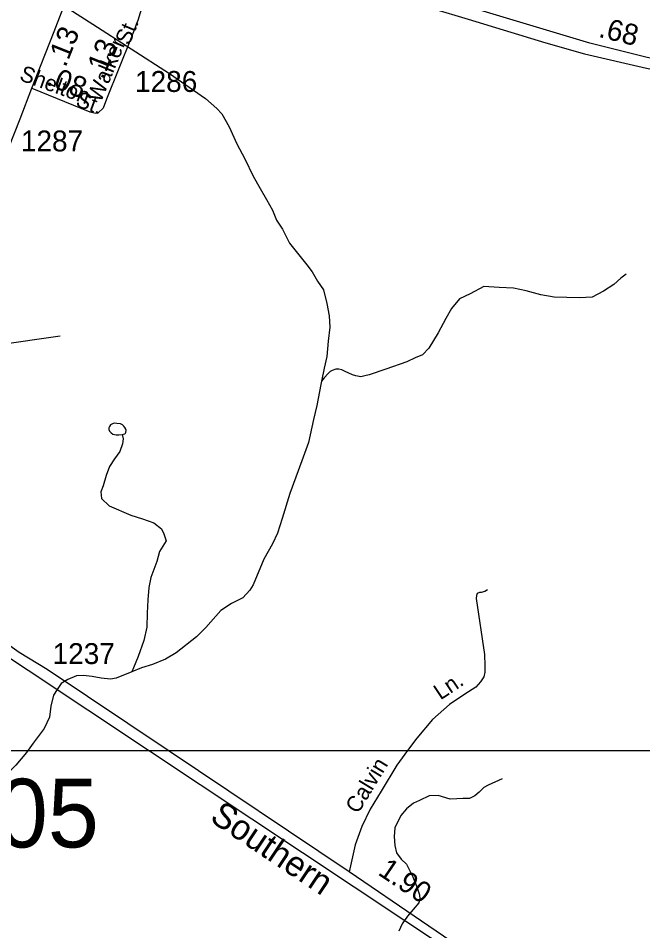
# Model space of a CAD drawing. Extents: x 2206922 to 2357709, y 510027 to 673830.
# Drawn here: x 2271615 to 2275344, y 609677 to 615129 of the extents above; entities that cross this region are included whole.
import ezdxf

# ---------------------------------------------------------------- set-up
doc = ezdxf.new("R2010")
doc.units = 0
for name, color, linetype in [('Exist Hydrographic Misc Water Feature', 7, 'Continuous'), ('Exist Railroad Mainline', 7, 'Continuous'), ('Exist Railroad Mainline Label', 7, 'Continuous'), ('Exist Road Non-System Type 51', 7, 'Continuous'), ('Exist Road Non-System Type 51 Label', 7, 'Continuous'), ('Exist Road Primary US Divided Attributed', 7, 'Continuous'), ('Exist Road Primary US Mileage Tenths English Label', 7, 'Continuous'), ('Exist Road Secondary Mileage Hundredths English Label', 7, 'Continuous'), ('Exist Road Secondary Structure Pipe Number Label', 7, 'Continuous'), ('Exist Road Secondary Type 51 Attributed', 7, 'Continuous'), ('Exist Road Secondary Type 51 Label', 7, 'Continuous'), ('Exist Road Secondary Type 51 Number Label', 7, 'Continuous'), ('Map Preparation Inset Cut Line', 7, 'Continuous')]:
    doc.layers.add(name, color=color, linetype=linetype)

msp = doc.modelspace()

# ---------------------------------------------------------------- linework, layer by layer
at = {"layer": 'Exist Hydrographic Misc Water Feature'}
for points in [[(2271915.8, 615185.7), (2272060.5, 615092.9), (2272517, 614799.5), (2272732.3, 614649.5), (2272800.6, 614590.5)], [(2272800.6, 614590.5), (2272831.1, 614556.7), (2272873.8, 614480.9), (2272920.7, 614377.7), (2272967.5, 614288), (2273016.5, 614184.4), (2273059.6, 614111), (2273097.5, 614045.3), (2273132.3, 613981.7), (2273157, 613922), (2273191.8, 613868.5), (2273234.3, 613784.6), (2273337.4, 613655.9), (2273370, 613614.1), (2273402.4, 613558.5), (2273436.6, 613506.7), (2273457.6, 613425.3), (2273471.9, 613351.3), (2273474.8, 613283.2), (2273465.4, 613199.4), (2273456.5, 613107.1), (2273441, 613037.2), (2273425.8, 612960.9)], [(2275244.8, 613599.6), (2275213.2, 613575.6), (2275171.6, 613537.3), (2275109.9, 613498.7), (2275042.2, 613461.9), (2274966.5, 613459.1), (2274890.3, 613460.4), (2274814.4, 613461.8), (2274736.1, 613477.2), (2274648.1, 613500.1), (2274572, 613515.7), (2274486.3, 613520.5), (2274394, 613525.9), (2274312.4, 613483), (2274248.9, 613452.5), (2274201.3, 613393.9), (2274167.7, 613335.7), (2274122.7, 613249.6), (2274065.7, 613156.8), (2274027.8, 613118.7), (2273984.3, 613100.1), (2273934.5, 613075.6), (2273809, 613032.5), (2273711, 612997.8), (2273683.3, 612991.4), (2273659.5, 612987.3), (2273631.2, 612993.2), (2273611.3, 612998.6), (2273567.5, 613018.2), (2273547, 613028.2), (2273528.9, 613032.1), (2273511.1, 613031.6), (2273489.3, 613023.5), (2273477.2, 613017.6), (2273465.6, 613005.6), (2273441.4, 612981.2), (2273425.8, 612960.9)], [(2273425.8, 612960.9), (2273424.1, 612951), (2273422.1, 612941.2), (2273397.1, 612814.7), (2273378, 612730.8), (2273347.2, 612594.3), (2273308.1, 612484.3), (2273236.1, 612289.5), (2273191.6, 612139.3), (2273162.3, 612052.8), (2273133, 611988.7), (2273081.9, 611896.2), (2273017.3, 611743.7), (2272998, 611711.8), (2272956.4, 611665.3), (2272888.3, 611632.6), (2272824.8, 611589.9), (2272735.8, 611489.3), (2272678.8, 611432.6), (2272557.6, 611337.7), (2272494.2, 611299), (2272416.3, 611268.6), (2272350.5, 611247.7), (2272292.9, 611223.1)], [(2272235.2, 612641.9), (2272251.2, 612646.4), (2272255.3, 612650.2), (2272257.4, 612654.4), (2272259.2, 612668.3), (2272256.8, 612674.3), (2272251.2, 612684.1), (2272244.9, 612691.9), (2272237.3, 612700), (2272224.8, 612705.9), (2272202.8, 612707.6), (2272190.7, 612709.4), (2272180.7, 612707.3), (2272172.9, 612703.2), (2272164.9, 612699.1), (2272159, 612689.5), (2272155.1, 612681.1), (2272155.3, 612671.4), (2272159, 612661.5), (2272169.2, 612651.4), (2272179.5, 612643.4), (2272199.6, 612639.5), (2272215.4, 612640), (2272235.2, 612641.9)], [(2272235.2, 612641.9), (2272241.6, 612616.2), (2272237.9, 612585.9), (2272220.5, 612539.9), (2272188.9, 612495.6), (2272159.4, 612451.4), (2272139.7, 612397.1), (2272122.7, 612335.2), (2272106.9, 612299.1), (2272110.8, 612259.1), (2272157.5, 612215.6), (2272286.1, 612160.5), (2272356.2, 612137.4), (2272424.1, 612114.2), (2272470.4, 612078.4), (2272485, 612048.6), (2272497.1, 612006.7), (2272457.9, 611942.4), (2272442.6, 611882.3), (2272405.6, 611788.1), (2272393.7, 611727.8), (2272388.8, 611654), (2272383.5, 611574), (2272382.3, 611489.9), (2272365, 611411.8), (2272330, 611315.7), (2272302.3, 611247.2), (2272292.9, 611223.1)], [(2272292.9, 611223.1), (2272199.6, 611186.5), (2272165.3, 611180.3), (2272109.3, 611185.5), (2272055.2, 611196.9), (2272002.9, 611202.7), (2271963.3, 611200.2), (2271911.7, 611177.6), (2271871.5, 611153.6), (2271847.9, 611119), (2271824.3, 611084.9), (2271809.1, 611018.7), (2271801.6, 610952.8), (2271768.5, 610884.5), (2271703.1, 610797.8), (2271664, 610741.6), (2271600, 610666.9), (2271542.8, 610606.6), (2271507.5, 610560.4), (2271475.7, 610501.9), (2271454.6, 610453.6), (2271430.4, 610234.3)], [(2274503.7, 610584.6), (2274420.3, 610547.7), (2274394, 610533.4), (2274366.4, 610505.1), (2274340.5, 610483), (2274308.5, 610466.8), (2274269, 610466.2), (2274234.5, 610464.1), (2274193.3, 610463.5), (2274123, 610485), (2274068.8, 610482.2), (2274011, 610455.6), (2273975.5, 610439.5), (2273933.7, 610405.2), (2273900.1, 610364.9), (2273862.7, 610292.7), (2273859.1, 610240.5), (2273863.8, 610186.7), (2273873.8, 610142.6), (2273900.7, 610104.8), (2273932.7, 610075.3), (2273971.2, 609999.8), (2273994, 609939.9), (2274010.2, 609892.1), (2274012.6, 609866.2), (2274006.9, 609844.3), (2273973.5, 609803.9), (2273939.4, 609763.6), (2273908.1, 609717.3), (2273886.5, 609675.1)]]:
    msp.add_lwpolyline(points, dxfattribs=at)
at = {"layer": 'Exist Railroad Mainline'}
msp.add_lwpolyline([(2277075.8, 607647), (2275362.6, 608781.5), (2275266.2, 608845.4), (2273928.2, 609731.4), (2272391.5, 610753.3), (2270229, 612191.5), (2265356.3, 615416.5), (2265047.6, 615620.9), (2265047, 615621.2)], dxfattribs=at)
at = {"layer": 'Exist Road Non-System Type 51'}
msp.add_line((2271864.9, 613228.8), (2271313.5, 613151.1), dxfattribs=at)
for points in [[(2274417.3, 611713), (2274401.3, 611702.9), (2274379.4, 611698.7), (2274369.4, 611698.5), (2274355.5, 611692.4), (2274351.7, 611680.3), (2274349.7, 611662.4), (2274398.9, 611327.1), (2274401.5, 611259), (2274399.9, 611221.1), (2274394.2, 611193), (2274374.4, 611164.8), (2274346.7, 611132.6), (2274281.3, 611089.9), (2274189.9, 611029.2), (2274088.7, 610938.3), (2273993.9, 610827.5), (2273939.3, 610753.3)], [(2273939.3, 610753.3), (2273875.5, 610666.5), (2273780.9, 610511.7), (2273716, 610403.1), (2273666.9, 610300.7), (2273626.1, 610190.4), (2273590.4, 610029)]]:
    msp.add_lwpolyline(points, dxfattribs=at)
at = {"layer": 'Exist Road Primary US Divided Attributed'}
for points in [[(2272279.8, 616185.2), (2272865.7, 615839.7), (2272898.5, 615819.6), (2273364.6, 615524.8), (2273529.8, 615425.2), (2273679, 615348.3), (2273792.1, 615291.7), (2273956.7, 615225.1), (2274088.2, 615186.5), (2274302.1, 615123.8), (2274764.8, 614981.6), (2274995.5, 614916), (2275366.5, 614830), (2275886.7, 614723.6), (2276257.7, 614639.9), (2276488.8, 614550.9), (2276574.4, 614508), (2276731.4, 614412.6)], [(2276769.4, 614472.2), (2276609.2, 614566.4), (2276511.3, 614613.8), (2276419.7, 614654.9), (2276282.5, 614701), (2275918.4, 614784.7), (2275371, 614893.3), (2275027.2, 614979.3), (2274371.2, 615176.3), (2274149.5, 615250.9), (2274108.8, 615262.3), (2274002.5, 615296.2), (2273891.7, 615330.2), (2273846.4, 615348.3), (2273776.3, 615382.2), (2273676.8, 615429.7), (2273491.3, 615527.1), (2273446.1, 615558.7), (2273384.4, 615595.7)]]:
    msp.add_lwpolyline(points, dxfattribs=at)
at = {"layer": 'Exist Road Secondary Type 51 Attributed'}
for points in [[(2271694.9, 614710.1), (2271829.2, 615049), (2271950.1, 615365.9)], [(2272357, 615206.5), (2272329.3, 615115.5), (2272289.8, 615012.7), (2272140.8, 614644.4), (2272121.5, 614590.6), (2272091, 614564.5)], [(2271557.9, 614356.7), (2271626.3, 614527.3), (2271694.9, 614710.1)], [(2271694.9, 614710.1), (2272042.5, 614569.7), (2272077.5, 614560.8), (2272091, 614564.5)], [(2277096.7, 607707.3), (2275318.8, 608849.9), (2273590.4, 610029), (2272510.7, 610753.3), (2271787.3, 611238.6), (2271619.8, 611340.2), (2271528.9, 611405.5)]]:
    msp.add_lwpolyline(points, dxfattribs=at)
at = {"layer": 'Map Preparation Inset Cut Line'}
for p, q in [((2269330.8, 610753.3), (2272391.5, 610753.3)), ((2272391.5, 610753.3), (2272510.7, 610753.3)), ((2272510.7, 610753.3), (2273939.3, 610753.3)), ((2273939.3, 610753.3), (2275588.8, 610753.3))]:
    msp.add_line(p, q, dxfattribs=at)

# ---------------------------------------------------------------- texts
at = {"layer": 'Exist Railroad Mainline Label'}
msp.add_text('Southern', height=150, rotation=326.1892, dxfattribs=at).set_placement((2272751.7, 610336.1))
at = {"layer": 'Exist Road Non-System Type 51 Label'}
for s, rotation, p in [('Ln.', 33.5879, (2274135.8, 611052.4)), ('Calvin', 58.6811, (2273643.2, 610370.9))]:
    msp.add_text(s, height=95, rotation=rotation, dxfattribs=at).set_placement(p)
at = {"layer": 'Exist Road Primary US Mileage Tenths English Label'}
msp.add_text('.68', height=125, rotation=345.9558, dxfattribs=at).set_placement((2275074.7, 615018.2))
at = {"layer": 'Exist Road Secondary Mileage Hundredths English Label'}
for s, rotation, p in [('.13', 68.3844, (2271897, 614830.8)), ('.13', 67.9655, (2272121.2, 614757.6)), ('.08', 338.0137, (2271776.5, 614733.8)), ('1.90', 325.9941, (2273756.8, 610015.8))]:
    msp.add_text(s, height=125, rotation=rotation, dxfattribs=at).set_placement(p)
at = {"layer": 'Exist Road Secondary Structure Pipe Number Label'}
msp.add_text('P205', height=410.1, dxfattribs=at).set_placement((2270815.6, 610174.8))
at = {"layer": 'Exist Road Secondary Type 51 Label'}
for s, rotation, p in [('St.', 67.5254, (2272277.4, 614963.1)), ('Walker', 67.5254, (2272107.3, 614620.4)), ('Shelton', 340.1568, (2271616.4, 614760.2)), ('St.', 340.1568, (2271952, 614605.4))]:
    msp.add_text(s, height=95, rotation=rotation, dxfattribs=at).set_placement(p)
at = {"layer": 'Exist Road Secondary Type 51 Number Label'}
for s, p in [('1286', (2272312, 614688.5)), ('1287', (2271630.3, 614333.1)), ('1237', (2271819.8, 611270.2))]:
    msp.add_text(s, height=125, dxfattribs=at).set_placement(p)

doc.saveas('drawing.dxf')
